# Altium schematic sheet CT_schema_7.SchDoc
size 408 x 245 mm
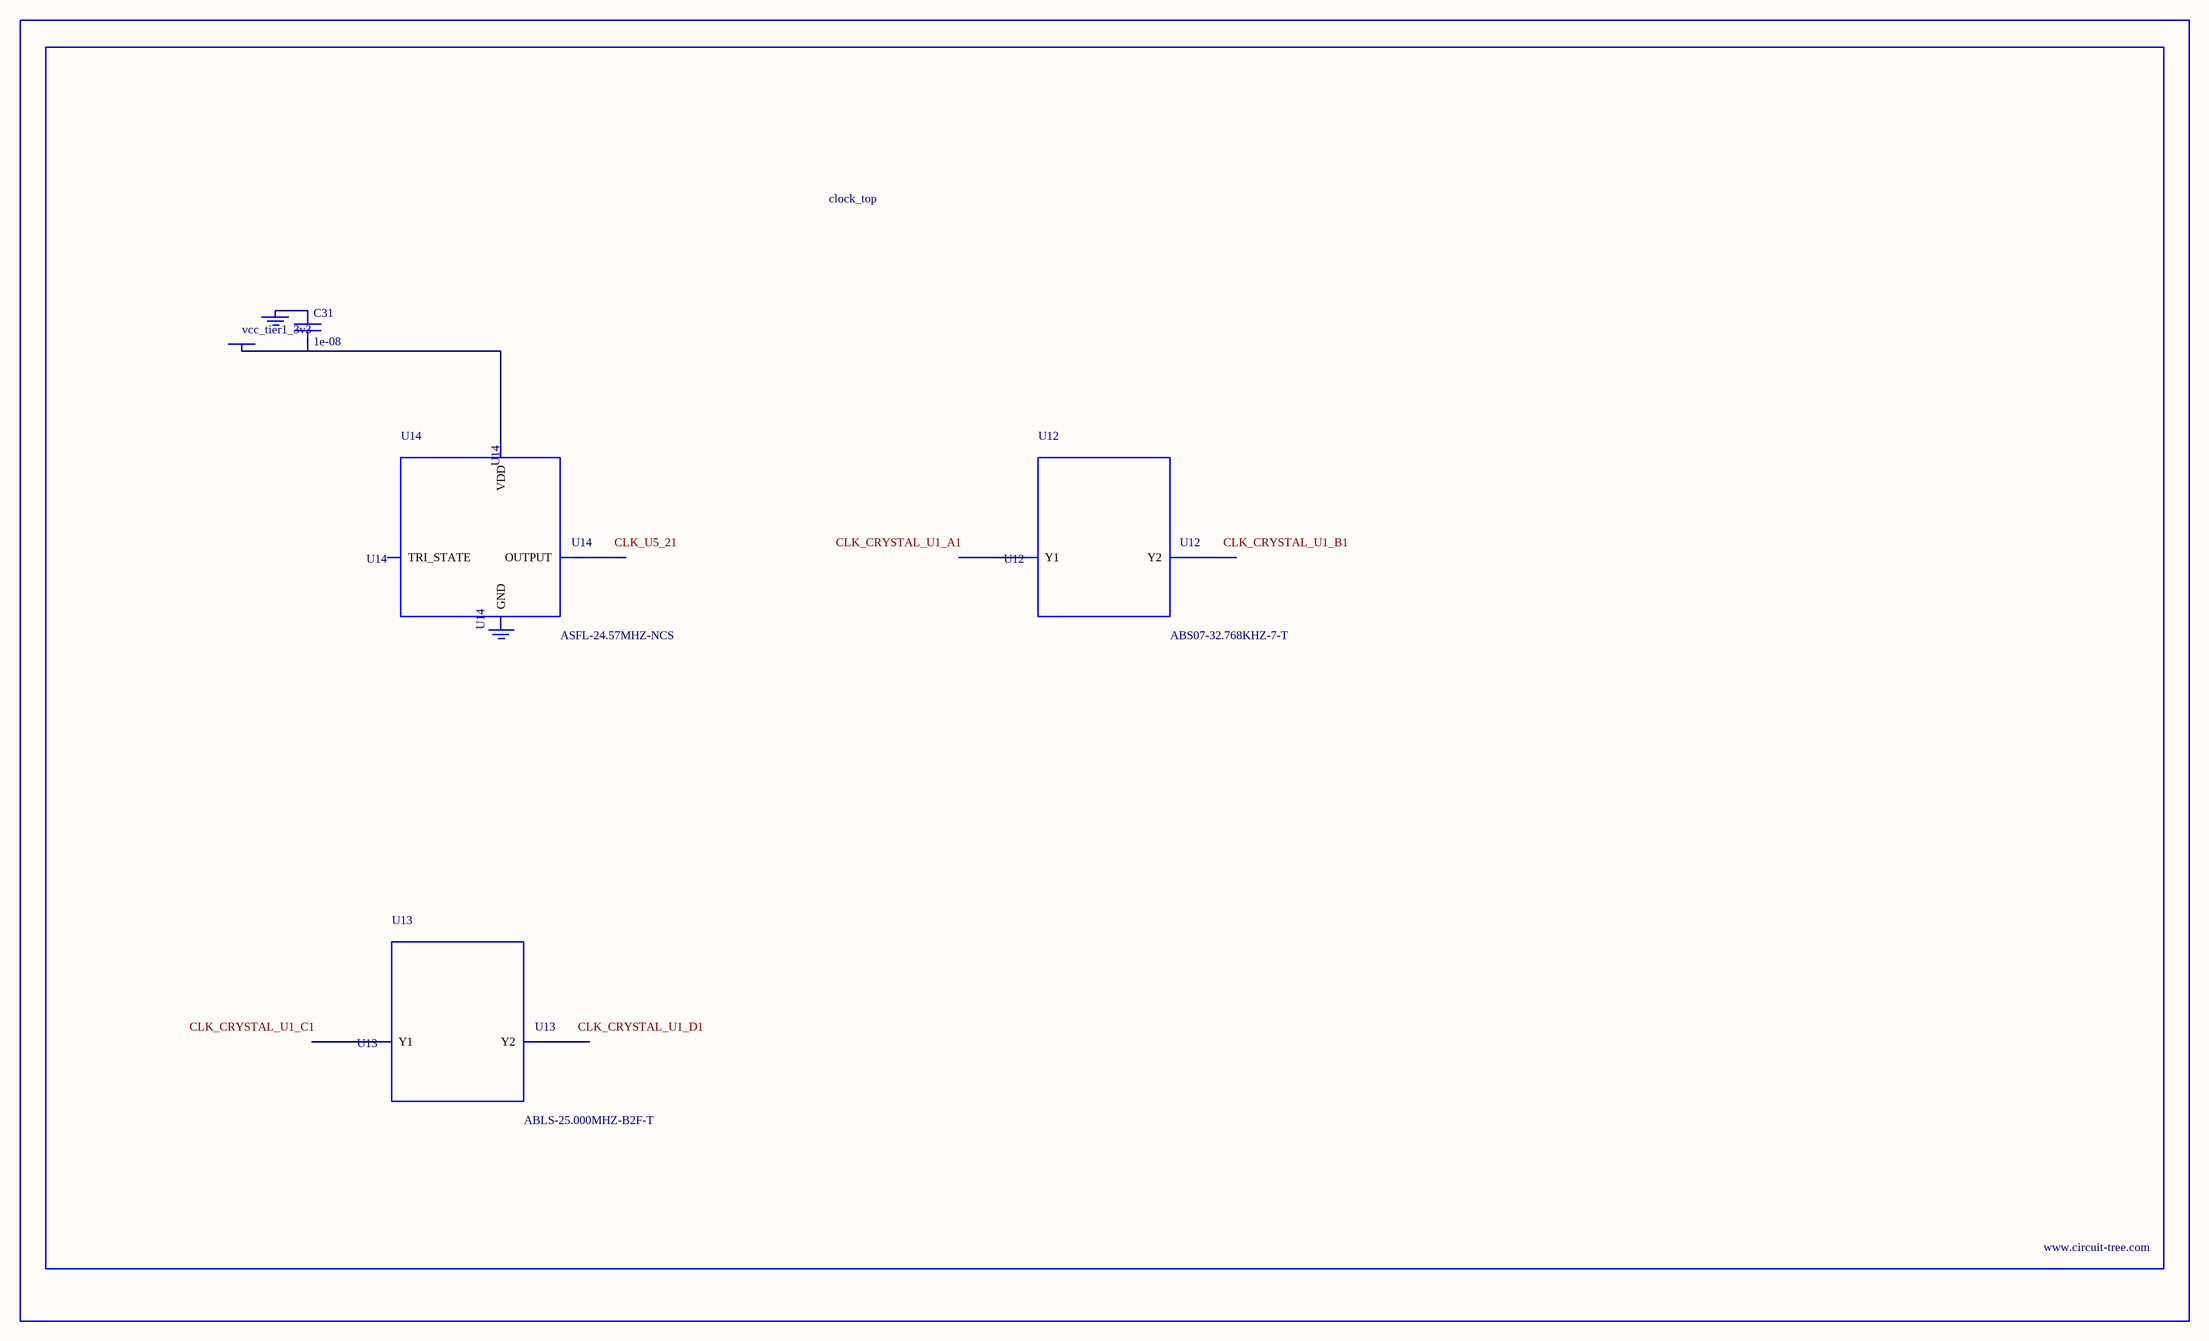
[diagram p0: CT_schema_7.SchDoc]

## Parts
BORDER6  (no value)
C31  1e-08  [C0402]
GND_INSTANCE_6_0  (no value)
GND_INSTANCE_6_1  (no value)
POWER_INSTANCE_6_0  vcc_tier1_3v3
U12  ABS07-32.768KHZ-7-T  [ABS07-32.768KHZ-7-T]
U13  ABLS-25.000MHZ-B2F-T  [ABLS-25.000MHZ-B2F-T]
U14  ASFL-24.57MHZ-NCS  [ASFL1]

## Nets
NetC31_1: C31.1 GND_INSTANCE_6_0.0(GND)
NetC31_2: C31.2 POWER_INSTANCE_6_0.0(PWR) U14.4(VDD)

Not connected (* = marked no-connect by the designer): GND_INSTANCE_6_1 0(GND); U12 1(Y1) 2(Y2); U13 1(Y1) 2(Y2); U14 1(TRI_STATE) 2(GND) 3(OUTPUT)

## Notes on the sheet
- Labels drawn without touching a wire or pin: CLK_CRYSTAL_U1_A1, CLK_CRYSTAL_U1_B1, CLK_CRYSTAL_U1_C1, CLK_CRYSTAL_U1_D1, CLK_U5_21

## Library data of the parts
BORDER6 = BORDER_PAGE6
C31 = C0402C103K3RAC
GND_INSTANCE_6_0 GND_INSTANCE_6_1 = GND
POWER_INSTANCE_6_0 = PWR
